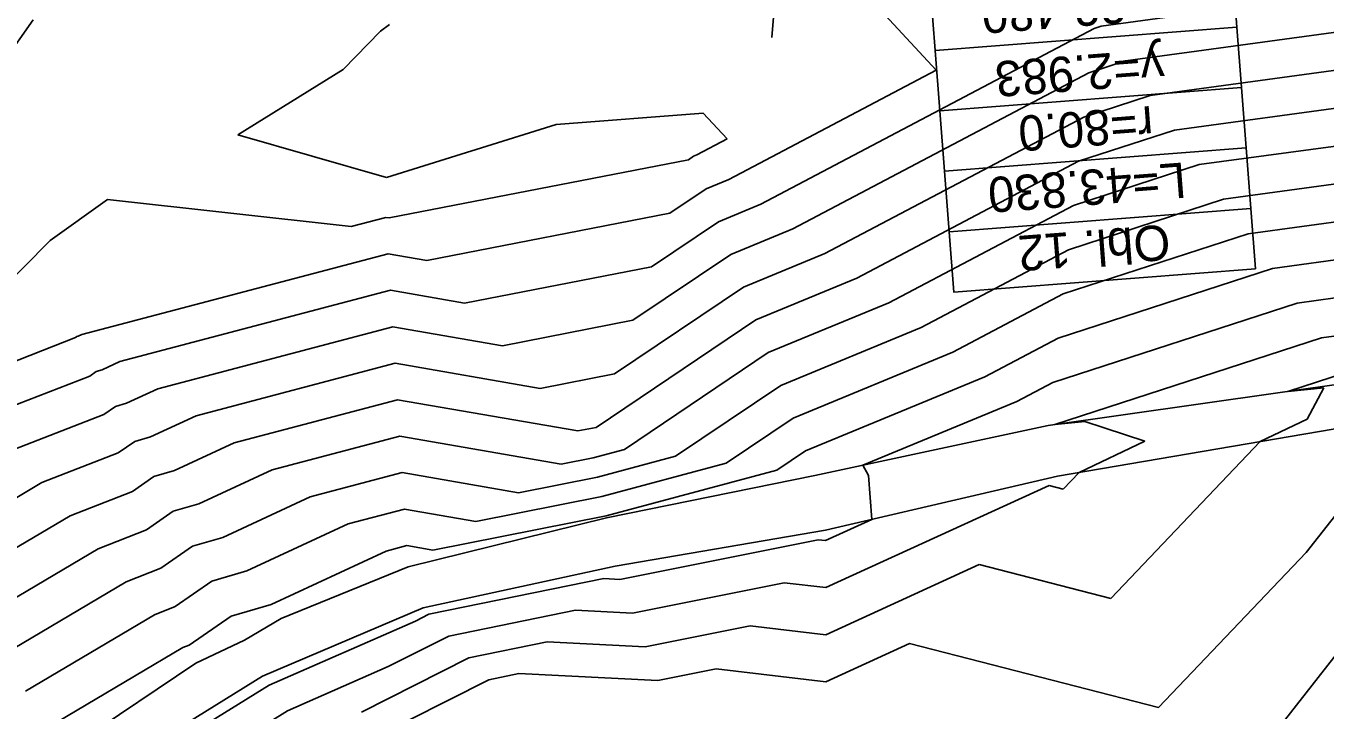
# Model space of a CAD drawing. Extents: x -549394 to -546608, y -1037055 to -1033629.
# Drawn here: x -548073.8 to -547944.9, y -1035575.9 to -1035508.1 of the extents above; entities that cross this region are included whole.
import ezdxf

# ---------------------------------------------------------------- set-up
doc = ezdxf.new("R2010")
doc.units = 0
for name, color, linetype in [('hlavni_vrst', 7, 'Continuous'), ('hrana_L', 7, 'Continuous'), ('norm_vrst', 7, 'Continuous'), ('x_popis_oblouky_C1', 7, 'Continuous')]:
    doc.layers.add(name, color=color, linetype=linetype)

msp = doc.modelspace()

# ---------------------------------------------------------------- linework, layer by layer
at = {"layer": 'hlavni_vrst'}
for p, q in [((-548038.63, -1035508.58), (-548037.74, -1035507.93)), ((-548042.35, -1035512.4), (-548038.63, -1035508.58)), ((-548052.76, -1035518.87), (-548042.35, -1035512.4)), ((-548006.66, -1035516.7), (-548021.22, -1035517.83)), ((-548004.28, -1035519.26), (-548006.66, -1035516.7)), ((-547959.92, -1035518.38), (-547941.82, -1035515.91)), ((-548021.22, -1035517.83), (-548038.03, -1035523.08)), ((-547969.44, -1035521.47), (-547959.92, -1035518.38)), ((-548038.03, -1035523.08), (-548052.76, -1035518.87)), ((-548007.27, -1035520.84), (-548004.28, -1035519.26)), ((-548008.12, -1035521.32), (-548007.6, -1035520.97)), ((-548007.6, -1035520.97), (-548007.27, -1035520.84)), ((-548037.79, -1035527.08), (-548008.12, -1035521.32)), ((-547991.41, -1035533.05), (-547969.44, -1035521.47)), ((-548071.37, -1035529.32), (-548065.71, -1035525.26)), ((-548065.71, -1035525.26), (-548041.55, -1035527.93)), ((-548041.55, -1035527.93), (-548038.11, -1035527.03)), ((-548038.11, -1035527.03), (-548037.79, -1035527.08)), ((-548081.43, -1035539.48), (-548071.37, -1035529.32)), ((-548001.44, -1035537.19), (-547991.41, -1035533.05)), ((-547947.79, -1035535.53), (-547942.12, -1035534.75)), ((-547971.98, -1035543.39), (-547947.79, -1035535.53)), ((-548017.27, -1035547.84), (-548001.44, -1035537.19)), ((-547975.55, -1035545.27), (-547971.98, -1035543.39)), ((-548053.15, -1035549.36), (-548036.95, -1035545.09)), ((-548036.95, -1035545.09), (-548019.06, -1035548.19)), ((-547990.84, -1035551.58), (-547975.55, -1035545.27)), ((-548019.06, -1035548.19), (-548017.27, -1035547.84)), ((-548059.04, -1035552.09), (-548053.15, -1035549.36)), ((-547990.26, -1035552.61), (-547990.84, -1035551.58)), ((-548063.23, -1035554.17), (-548061.09, -1035552.69)), ((-548061.09, -1035552.69), (-548059.04, -1035552.09)), ((-547989.92, -1035556.95), (-547990.26, -1035552.61)), ((-548069.41, -1035556.58), (-548063.23, -1035554.17)), ((-548077.48, -1035561.37), (-548069.41, -1035556.58)), ((-547994.52, -1035559.05), (-547989.92, -1035556.95)), ((-548014.9, -1035562.89), (-547995.26, -1035558.96)), ((-547995.26, -1035558.96), (-547994.52, -1035559.05)), ((-548033.83, -1035566.34), (-548016.49, -1035562.81)), ((-548016.49, -1035562.81), (-548014.9, -1035562.89)), ((-548049.67, -1035573.38), (-548035.18, -1035567.02)), ((-548035.18, -1035567.02), (-548033.83, -1035566.34)), ((-548068.19, -1035584.8), (-548049.67, -1035573.38))]:
    msp.add_line(p, q, dxfattribs=at)
at = {"layer": 'hrana_L'}
for p, q in [((-547942.25, -1035543.35), (-547972.47, -1035547.64)), ((-547972.47, -1035547.64), (-547995.58, -1035552.59)), ((-547971.54, -1035552.66), (-547942.64, -1035547.74)), ((-547995.58, -1035552.59), (-548016.23, -1035556.8)), ((-547994.52, -1035558.02), (-547971.54, -1035552.66)), ((-548016.23, -1035556.8), (-548035.89, -1035561.64)), ((-548015.39, -1035561.59), (-547994.52, -1035558.02)), ((-548035.89, -1035561.64), (-548048.48, -1035566.77)), ((-548034.4, -1035565.71), (-548015.39, -1035561.59)), ((-548050.32, -1035572.47), (-548034.4, -1035565.71)), ((-548052.12, -1035568.92), (-548048.48, -1035566.77)), ((-548052.12, -1035568.92), (-548056.93, -1035571.19)), ((-548056.93, -1035571.19), (-548071.74, -1035581.11)), ((-548070.83, -1035585.15), (-548050.32, -1035572.47))]:
    msp.add_line(p, q, dxfattribs=at)
at = {"layer": 'norm_vrst'}
for p, q in [((-547983.55, -1035512.45), (-547991.06, -1035504.34)), ((-547967.21, -1035508.09), (-547941.64, -1035504.6)), ((-548075.93, -1035511.56), (-548073.07, -1035507.45)), ((-547967.91, -1035508.32), (-547967.21, -1035508.09)), ((-548000.93, -1035525.72), (-547967.91, -1035508.32)), ((-547964.78, -1035511.52), (-547941.7, -1035508.37)), ((-547968.42, -1035512.71), (-547964.78, -1035511.52)), ((-548004.1, -1035523.28), (-547983.55, -1035512.45)), ((-547997.75, -1035528.17), (-547968.42, -1035512.71)), ((-547962.35, -1035514.95), (-547941.76, -1035512.14)), ((-547968.93, -1035517.09), (-547962.35, -1035514.95)), ((-547994.58, -1035530.61), (-547968.93, -1035517.09)), ((-547957.5, -1035521.81), (-547941.88, -1035519.68)), ((-547969.94, -1035525.86), (-547957.5, -1035521.81)), ((-548006.37, -1035524.21), (-548004.1, -1035523.28)), ((-547955.07, -1035525.24), (-547941.94, -1035523.45)), ((-548009.95, -1035526.63), (-548006.37, -1035524.21)), ((-548005.13, -1035527.46), (-548000.93, -1035525.72)), ((-547988.24, -1035535.5), (-547969.94, -1035525.86)), ((-547970.45, -1035530.24), (-547955.07, -1035525.24)), ((-548034.05, -1035531.3), (-548009.95, -1035526.63)), ((-548011.78, -1035531.93), (-548005.13, -1035527.46)), ((-547952.64, -1035528.67), (-547942, -1035527.22)), ((-548003.9, -1035530.7), (-547997.75, -1035528.17)), ((-547970.96, -1035534.62), (-547952.64, -1035528.67)), ((-548068.23, -1035538.63), (-548037.88, -1035530.64)), ((-548037.88, -1035530.64), (-548034.05, -1035531.3)), ((-548013.61, -1035537.23), (-548003.9, -1035530.7)), ((-548002.67, -1035533.94), (-547994.58, -1035530.61)), ((-547985.06, -1035537.94), (-547970.45, -1035530.24)), ((-547950.21, -1035532.1), (-547942.06, -1035530.98)), ((-548030.3, -1035535.52), (-548011.78, -1035531.93)), ((-547971.47, -1035539), (-547950.21, -1035532.1)), ((-548064.46, -1035541.32), (-548037.65, -1035534.25)), ((-548037.65, -1035534.25), (-548030.3, -1035535.52)), ((-548015.44, -1035542.54), (-548002.67, -1035533.94)), ((-547981.89, -1035540.38), (-547970.96, -1035534.62)), ((-548000.2, -1035540.43), (-547988.24, -1035535.5)), ((-548026.55, -1035539.75), (-548013.61, -1035537.23)), ((-548080.58, -1035543.51), (-548068.87, -1035538.94)), ((-548068.87, -1035538.94), (-548068.73, -1035538.84)), ((-548068.73, -1035538.84), (-548068.6, -1035538.81)), ((-548068.6, -1035538.81), (-548068.23, -1035538.63)), ((-548060.69, -1035544), (-548037.41, -1035537.86)), ((-548037.41, -1035537.86), (-548026.55, -1035539.75)), ((-547998.97, -1035543.67), (-547985.06, -1035537.94)), ((-547978.72, -1035542.83), (-547971.47, -1035539)), ((-547971.78, -1035547.54), (-547945.36, -1035538.96)), ((-547945.36, -1035538.96), (-547942.17, -1035538.52)), ((-548066.21, -1035542.13), (-548064.46, -1035541.32)), ((-548056.92, -1035546.68), (-548037.18, -1035541.48)), ((-548037.18, -1035541.48), (-548022.81, -1035543.97)), ((-548014.44, -1035550.01), (-548000.2, -1035540.43)), ((-547997.74, -1035546.91), (-547981.89, -1035540.38)), ((-548077.79, -1035546.77), (-548067.46, -1035542.75)), ((-548067.46, -1035542.75), (-548066.82, -1035542.31)), ((-548066.82, -1035542.31), (-548066.21, -1035542.13)), ((-548022.81, -1035543.97), (-548015.44, -1035542.54)), ((-547996.5, -1035550.16), (-547978.72, -1035542.83)), ((-547948.71, -1035544.27), (-547942.93, -1035542.39)), ((-548063.82, -1035545.45), (-548060.69, -1035544)), ((-548009.41, -1035550.7), (-547998.97, -1035543.67)), ((-547945.14, -1035543.92), (-547948.71, -1035544.27)), ((-547946.79, -1035547.02), (-547945.14, -1035543.92)), ((-548064.91, -1035545.77), (-548063.82, -1035545.45)), ((-548074.99, -1035550.04), (-548066.05, -1035546.55)), ((-548066.05, -1035546.55), (-548064.91, -1035545.77)), ((-548061.43, -1035548.77), (-548056.92, -1035546.68)), ((-548004.38, -1035551.39), (-547997.74, -1035546.91)), ((-547968.82, -1035547.26), (-547971.78, -1035547.54)), ((-547962.89, -1035549.19), (-547968.82, -1035547.26)), ((-547951.44, -1035549.24), (-547946.79, -1035547.02)), ((-548064.64, -1035550.36), (-548063, -1035549.23)), ((-548063, -1035549.23), (-548061.43, -1035548.77)), ((-548049.38, -1035552.04), (-548036.72, -1035548.7)), ((-548036.72, -1035548.7), (-548020.74, -1035551.47)), ((-547969.39, -1035552.29), (-547962.89, -1035549.19)), ((-547966.24, -1035564.77), (-547951.44, -1035549.24)), ((-548072.2, -1035553.31), (-548064.64, -1035550.36)), ((-548017.57, -1035550.84), (-548014.44, -1035550.01)), ((-547999.35, -1035552.07), (-547996.5, -1035550.16)), ((-548020.74, -1035551.47), (-548017.57, -1035550.84)), ((-548017.14, -1035552.76), (-548009.41, -1035550.7)), ((-548016.71, -1035554.67), (-548004.38, -1035551.39)), ((-548056.65, -1035555.41), (-548049.38, -1035552.04)), ((-548045.62, -1035554.72), (-548036.49, -1035552.32)), ((-548036.49, -1035552.32), (-548024.97, -1035554.31)), ((-548024.97, -1035554.31), (-548017.14, -1035552.76)), ((-548016.28, -1035556.59), (-547999.35, -1035552.07)), ((-547970.97, -1035553.96), (-547969.39, -1035552.29)), ((-547946.89, -1035560.24), (-547940.97, -1035552.68)), ((-548078.7, -1035557.17), (-548072.2, -1035553.31)), ((-547994.51, -1035563.71), (-547972.37, -1035553.6)), ((-547972.37, -1035553.6), (-547970.97, -1035553.96)), ((-548059.17, -1035556.15), (-548056.65, -1035555.41)), ((-548054.26, -1035558.73), (-548045.62, -1035554.72)), ((-548029.2, -1035557.15), (-548016.71, -1035554.67)), ((-548061.82, -1035557.98), (-548059.17, -1035556.15)), ((-548041.85, -1035557.4), (-548036.26, -1035555.93)), ((-548036.26, -1035555.93), (-548029.2, -1035557.15)), ((-548033.44, -1035559.99), (-548016.28, -1035556.59)), ((-548066.62, -1035559.85), (-548061.82, -1035557.98)), ((-548051.87, -1035562.05), (-548041.85, -1035557.4)), ((-548060.41, -1035561.78), (-548057.26, -1035559.61)), ((-548057.26, -1035559.61), (-548054.26, -1035558.73)), ((-548038.08, -1035560.08), (-548036.02, -1035559.54)), ((-548036.02, -1035559.54), (-548033.44, -1035559.99)), ((-548076.26, -1035565.57), (-548066.62, -1035559.85)), ((-548049.48, -1035565.38), (-548038.08, -1035560.08)), ((-547961.52, -1035575.59), (-547946.89, -1035560.24)), ((-548063.83, -1035563.12), (-548060.41, -1035561.78)), ((-548055.35, -1035563.07), (-548051.87, -1035562.05)), ((-547994.5, -1035568.38), (-547979.28, -1035561.42)), ((-547979.28, -1035561.42), (-547966.24, -1035564.77)), ((-548075.04, -1035569.77), (-548063.83, -1035563.12)), ((-548059, -1035565.59), (-548055.35, -1035563.07)), ((-548013.66, -1035566.24), (-547998.64, -1035563.23)), ((-547998.64, -1035563.23), (-547994.51, -1035563.71)), ((-547955.22, -1035584.76), (-547937.68, -1035562.37)), ((-548061.03, -1035566.39), (-548059, -1035565.59)), ((-548053.44, -1035566.53), (-548049.48, -1035565.38)), ((-548031.85, -1035568.5), (-548019.3, -1035565.95)), ((-548019.3, -1035565.95), (-548013.66, -1035566.24)), ((-548073.82, -1035573.97), (-548061.03, -1035566.39)), ((-548057.59, -1035569.4), (-548053.44, -1035566.53)), ((-548037.86, -1035571.52), (-548031.85, -1035568.5)), ((-548012.41, -1035569.58), (-548002.01, -1035567.5)), ((-548002.01, -1035567.5), (-547994.5, -1035568.38)), ((-548072.6, -1035578.17), (-548058.24, -1035569.65)), ((-548058.24, -1035569.65), (-548057.59, -1035569.4)), ((-548029.87, -1035570.66), (-548022.11, -1035569.09)), ((-548022.11, -1035569.09), (-548012.41, -1035569.58)), ((-547994.49, -1035573.04), (-547986.19, -1035569.25)), ((-547986.19, -1035569.25), (-547961.52, -1035575.59)), ((-548040.53, -1035576.03), (-548029.87, -1035570.66)), ((-548047.86, -1035575.92), (-548037.86, -1035571.52)), ((-548027.9, -1035572.83), (-548024.93, -1035572.22)), ((-548024.93, -1035572.22), (-548011.16, -1035572.92)), ((-548011.16, -1035572.92), (-548005.38, -1035571.76)), ((-548005.38, -1035571.76), (-547994.49, -1035573.04)), ((-548043.21, -1035580.53), (-548027.9, -1035572.83)), ((-548060.65, -1035583.8), (-548047.86, -1035575.92))]:
    msp.add_line(p, q, dxfattribs=at)
at = {"layer": 'x_popis_oblouky_C1'}
msp.add_lwpolyline([(-547996.43, -1035468), (-547999.84, -1035509.23)], dxfattribs=at)
for points in [[(-547953.74, -1035508.2), (-547983.65, -1035510.5), (-547984.11, -1035504.52), (-547954.2, -1035502.21)], [(-547953.28, -1035514.18), (-547983.19, -1035516.48), (-547983.65, -1035510.5), (-547953.74, -1035508.2)], [(-547952.82, -1035520.16), (-547982.73, -1035522.46), (-547983.19, -1035516.48), (-547953.28, -1035514.18)], [(-547952.36, -1035526.14), (-547982.27, -1035528.45), (-547982.73, -1035522.46), (-547952.82, -1035520.16)], [(-547951.9, -1035532.13), (-547981.81, -1035534.43), (-547982.27, -1035528.45), (-547952.36, -1035526.14)]]:
    msp.add_lwpolyline(points, close=True, dxfattribs=at)

# ---------------------------------------------------------------- texts
for s, p in [('t=22.480', (-547960.88, -1035503.94)), ('y=2.983', (-547961.09, -1035510.33)), ('r=80.0', (-547962.17, -1035515.98)), ('L=43.830', (-547958.94, -1035521.58)), ('Obl. 12', (-547960.51, -1035527.72))]:
    msp.add_text(s, height=3.5, rotation=184.4206, dxfattribs=at).set_placement(p)

doc.saveas('drawing.dxf')
